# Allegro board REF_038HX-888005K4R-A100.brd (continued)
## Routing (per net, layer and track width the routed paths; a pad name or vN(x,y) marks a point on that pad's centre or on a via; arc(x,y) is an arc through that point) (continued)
1SK1_2: length 3.3
  TOP w0.231: UNK1SK1_2.1 249.83,182.77 UNK2SK1.2
1SK1_3: length 3
  TOP w0.231: UNK2SK1.3 UNK1SK1_3.1
1SK1_4: length 3.3
  TOP w0.231: UNK1SK1_4.1 249.83,188.79 UNK2SK1.4
1SK1_5: length 3.3
  TOP w0.231: UNK2SK1.5 254.65,188.79 UNK1SK1_5.1
1SK1_6: length 3
  TOP w0.231: UNK2SK1.6 UNK1SK1_6.1
1SK1_7: length 3.3
  TOP w0.231: UNK2SK1.7 254.65,182.77 UNK1SK1_7.1
1SK2_2: length 3.3
  TOP w0.231: UNK2SK2.2 266.34,182.77 UNK1SK2_2.1
1SK2_3: length 3
  TOP w0.231: UNK2SK2.3 UNK1SK2_3.1
1SK2_4: length 3.3
  TOP w0.231: UNK2SK2.4 266.34,188.79 UNK1SK2_4.1
1SK2_5: length 3.3
  TOP w0.231: UNK2SK2.5 271.16,188.79 UNK1SK2_5.1
1SK2_6: length 3
  TOP w0.231: UNK2SK2.6 UNK1SK2_6.1
1SK2_7: length 3.3
  TOP w0.231: UNK2SK2.7 271.16,182.77 UNK1SK2_7.1
CSDPS225GS1: length 221.9
  L18_POWER w0.203: SH2.2 83.05,204.25 75.9,211.4 75.9,230.22 72.28,233.83 72.28,298.16 95.49,321.36 95.49,348.54 96.17,349.22 123.34,349.22 126.06,346.5 126.06,328.87 CSDPS225.D2
CSDPS225GS3: length 96.7
  L11_POWER w0.203: CSDPS225.D4 136.19,313.65 136.19,255.89 134.92,254.62 134.92,239.9 136.33,238.49 SH24.2
CSDPS225GS5: length 117.7
  L14_POWER w0.203: SH13.2 140.82,248.47 141.96,249.62 141.96,251.82 141.52,252.27 141.52,262.31 131.87,271.96 131.87,334.79 130.27,336.39 116.51,336.39 116.01,335.88 116.01,328.76 CSDPS225.D6
CSDPS225GS7: length 96.5
  L16_POWER w0.203: CSDPS225.D8 112.03,322.44 106.91,317.32 106.91,241.73 109.74,238.9 111.81,238.9 112.66,238.05 SH8.2
CSDPS225GS9: length 186.7
  L09_POWER w0.203: SH26.2 101.66,220.34 99.34,218.02 94.61,218.02 91.99,220.65 75.25,220.65 56.67,239.23 56.67,244.65 51.45,249.87 51.45,251.38 48.13,254.7 48.13,291.4 78.84,322.11 101.4,322.11 CSDPS225.D10
CSDPS225GS11: length 145.7
  L14_POWER w0.203: CSDPS225.D12 104.1,325.43 109.92,325.43 110.92,326.43 110.92,340.61 111.86,341.55 132.11,341.55 133.05,340.61 133.05,272.45 143.87,261.63 143.87,253.56 144.32,253.11 SH15.2
CSDPS225GS13: length 225.3
  L09_POWER w0.203: SH6.2 155.68,213.34 156.32,213.97 156.32,228.24 155.72,228.84 155.72,257.92 153.76,259.88 153.76,287.44 146.76,294.43 146.76,339.29 134.19,351.86 106.81,351.86 105.75,350.8 105.75,327.58 104.67,326.51 97.94,326.51 CSDPS225.D14
  L13_CBIT w0.203: CSDPS225.A13 98.06,334.01 98.06,328.93 CSDPS225.D14 95.52,328.93 92.98,328.93 CSDPS225.D16
CSDPS225P1: length 35.2
  TOP w0.231: SITE1.3 118.52,200.86 117.21,199.55 116.14,199.55
  TOP w0.508: v1(113.47,195.75) 113.47,196.88 116.14,199.55
  L18_POWER w0.203: SH1.1 97.83,205.26 98.16,204.94 109.52,204.94 110.61,206.03 110.61,207.1 111.54,208.02 117.44,208.02 v1(118.77,206.69)
  vias: v1(94.6,264.49) v1(94.6,262.58) v1(111.81,192.9) v1(113.47,193.71)
CSDPS225P3: length 28.7
  TOP w0.231: 128.36,231.45 128.36,231.11 128.52,230.95 SITE1.105
  TOP w0.381: 128.36,231.45 128.36,233.59 129.21,234.45 v1(129.21,234.54)
  L11_POWER w0.203: v1(129.43,223.59) 130.55,222.47 132.41,222.47 134.57,224.64 134.57,231.98 137.34,234.76 SH23.1
  vias: v1(78.3,264.49) v1(78.3,262.58) v1(129.21,236.58)
CSDPS225P5: length 44
  TOP w0.231: SITE1.106 128.12,230.53 127.75,230.9 127.75,231.12
  TOP w0.381: 127.75,231.12 127.75,233.82 128.32,234.39 v1(128.32,234.54)
  L14_POWER w0.203: v1(128.23,223.59) 127.56,222.92 127.56,222.17 127.96,221.76 132.81,221.76 139.38,228.33 139.38,237.15 140.69,238.47 140.69,244.2 141.84,245.35 SH14.1
  vias: v1(78.3,244.17) v1(78.3,242.26) v1(128.32,236.58) v1(129.1,237.66)
CSDPS225P7: length 45
  TOP w0.231: SITE1.25 127.32,200.56 126.77,200.01
  TOP w0.508: v1(126.55,195.75) 126.55,198.68 126.77,198.9 126.77,200.01
  L16_POWER w0.203: SH7.1 113.68,227.62 121.76,219.55 121.76,208.6 122.56,207.8 126.46,207.8 v1(127.57,206.69)
  vias: v1(61.99,284.81) v1(61.99,282.9) v1(126.55,193.71)
CSDPS225P9: length 37.5
  TOP w0.231: 123.13,228.01 122.92,227.79 SITE1.119 ; SITE1.139 110.36,220.83 107.5,223.69 v1(106.93,223.69)
  TOP w0.508: 123.13,228.01 123.13,234.47 v1(123.06,234.54)
  L09_POWER w0.203: SH25.1 121.83,221.14 122.85,222.17 122.85,222.89 v1(122.16,223.59)
  vias: v1(51.85,264.49) v1(51.85,262.58) v1(104.89,223.69) v1(123.06,236.58)
CSDPS225P11: length 49.4
  TOP w0.231: 126.54,231.13 126.54,230.57 126.12,230.15 SITE1.111
  TOP w0.381: 126.54,231.13 v1(126.54,234.54)
  L14_POWER w0.203: SH16.1 145.33,240.67 140.56,235.9 140.56,227.84 133.83,221.1 125.84,221.1 125.24,221.7 125.24,222.71 v1(126.12,223.59)
  vias: v1(68.57,244.17) v1(68.57,242.26) v1(126.54,236.58) v1(130.1,240.04)
CSDPS225P13: length 50.6
  TOP w0.231: SITE1.64 141.98,213.63 ; 108.73,217.18 109.19,217.63 SITE1.147 ; SITE1.104 128.92,233.21 ; SITE1.39 132.92,201.49 134.03,200.37 136.06,200.37 ; SITE1.22 126.12,200.54
  TOP w0.381: 128.92,233.21 130.1,234.39 v1(130.1,234.54)
  TOP w0.508: v1(125.66,195.75) 125.66,198.96 125.87,199.17 125.87,200.28 126.12,200.54 ; 108.73,217.18 108.21,216.66 v1(106.93,216.66) ; 141.98,213.63 142.98,213.63 143.97,212.64 v1(146.71,212.64) ; v1(139.12,195.75) 139.12,197.31 136.06,200.37
  L09_POWER w0.203: v1(148.75,212.64) 148.86,212.54 SH5.1
  vias: v1(61.99,223.85) v1(61.99,221.94) v1(104.89,216.66) v1(125.66,193.71) v1(130.1,236.58) v1(134.48,213.47) v1(139.12,193.71)
CSDPS225PS1: length 219.3
  L18_POWER w0.203: SH1.2 83.04,205.26 76.61,211.7 76.61,230.68 73.07,234.22 73.07,297.93 98.11,322.97 98.11,345.75 98.79,346.42 122.6,346.42 123.41,345.61 123.41,326.84 124.27,325.98 128.13,325.98 CSDPS225.D1
CSDPS225PS3: length 96.4
  L11_POWER w0.203: SH23.2 137.34,239.05 136.83,239.56 136.83,248.36 137.21,248.73 137.21,254.5 138.43,255.72 138.43,313.96 CSDPS225.D3
CSDPS225PS5: length 133.7
  L14_POWER w0.203: CSDPS225.D5 117.84,325.85 113.92,325.85 113.41,326.36 113.41,338.27 114.14,339.01 130.6,339.01 132.45,337.15 132.45,272.2 142.1,262.55 142.1,252.51 142.54,252.06 142.54,249.19 141.84,248.48 SH14.2
CSDPS225PS7: length 97.3
  L16_POWER w0.203: CSDPS225.D7 114.57,323.94 107.65,317.01 107.65,242.04 110.05,239.64 112.12,239.64 113.68,238.08 SH7.2
CSDPS225PS9: length 186.6
  L09_POWER w0.203: CSDPS225.D9 103.07,321.24 79.2,321.24 49,291.04 49,255.06 52.32,251.74 52.32,250.23 57.54,245.01 57.54,239.59 75.61,221.52 92.35,221.52 94.97,218.89 98.98,218.89 101.23,221.14 SH25.2
CSDPS225PS11: length 148.3
  L14_POWER w0.203: SH16.2 145.33,261.03 133.66,272.7 133.66,343.41 132.95,344.11 108.69,344.11 107.98,343.41 107.98,326.9 107.38,326.3 105.77,326.3 CSDPS225.D11
CSDPS225PS13: length 232.3
  L09_POWER w0.203: SH5.2 156.29,212.54 157.14,213.39 157.14,257.82 154.7,260.27 154.7,287.83 147.71,294.82 147.71,339.68 132.98,354.41 104.04,354.41 103.16,353.54 103.16,329.54 102.55,328.92 101.45,328.92 100.19,327.66 CSDPS225.D13
  L13_CBIT w0.203: CSDPS225.A14 98.26,336.75 100.24,336.75 100.6,336.39 100.6,328.93 CSDPS225.D13 97.9,326.24 95.67,326.24 CSDPS225.D15
CSDPS229GS1: length 448.5
  L18_POWER w0.203: CSDPS229.D2 52.4,328.87 52.4,346.5 49.68,349.22 22.51,349.22 21.83,348.54 21.83,296.94 22.79,295.97 22.79,187.62 25.99,184.42 25.99,164.74 39.32,151.41 109.84,151.41 114.05,147.2 157.56,147.2 160.43,150.07 160.43,152.82 162.53,154.92 162.53,157.27 174.67,169.41 177.61,169.41 180.89,172.68 180.89,196.48 185.35,200.95 185.35,205.55 185.62,205.83 2SH2.2
CSDPS229GS3: length 243.7
  L11_POWER w0.203: 2SH24.2 216.33,238.76 214.91,240.17 214.91,254.37 169.51,299.77 169.51,313.27 130.8,351.98 84.22,351.98 57.74,325.5 50.69,325.5 CSDPS229.D4
CSDPS229GS5: length 263.7
  L14_POWER w0.203: CSDPS229.D6 42.21,328.9 42.21,340.93 42.91,341.63 57.3,341.63 62.42,346.74 137.32,346.74 161.42,322.64 192.45,322.64 218.09,297 218.09,260.47 219.1,259.46 219.1,255.13 220.82,253.41 2SH13.2
CSDPS229GS7: length 317.7
  L16_POWER w0.203: 2SH8.2 196.87,194.24 193.02,190.39 189.72,190.39 188.42,189.09 188.42,186.42 186.53,184.53 183.42,184.53 168.41,169.52 118.9,169.52 118.38,170.04 57.77,170.04 51.45,176.35 51.45,193.8 40.26,204.99 40.26,296.13 38.37,298.02 CSDPS229.D8
CSDPS229GS9: length 376.1
  L09_POWER w0.203: 2SH26.2 182.91,220.34 179.51,216.94 179.51,209.47 180.58,208.4 180.58,183.02 174.37,176.81 172.91,176.81 163.45,167.34 117.06,167.34 115.76,166.05 36.14,166.05 31.53,170.66 31.53,224.12 28.49,227.16 20.53,227.16 13.31,234.37 13.31,289.03 13.72,289.43 13.72,291.81 13.31,292.22 13.31,302.83 33.29,322.8 CSDPS229.D10
CSDPS229GS11: length 289.6
  L14_POWER w0.203: CSDPS229.D12 30.44,325.43 36.5,325.43 37.3,326.23 37.3,346.14 37.87,346.71 56.64,346.71 61.72,351.79 133.94,351.79 161.91,323.82 192.94,323.82 219.27,297.49 219.27,260.96 220.29,259.95 220.29,255.61 224.32,251.58 2SH15.2
CSDPS229GS13: length 389.7
  L09_POWER w0.203: 2SH6.2 237.8,213.47 246.49,222.16 246.49,295.89 231.96,310.42 174.54,310.42 157.35,327.61 157.35,341 136.39,361.96 70.17,361.96 60.07,351.86 33.15,351.86 32.09,350.8 32.09,327.58 31.01,326.51 24.28,326.51 CSDPS229.D14
  L13_CBIT w0.203: CSDPS229.A13 24.4,334.01 24.4,328.93 CSDPS229.D14 21.86,328.93 19.32,328.93 CSDPS229.D16
CSDPS229P1: length 22.2
  TOP w0.231: 196.14,199.55 197.21,199.55 198.52,200.86 SITE2.3
  TOP w0.508: 196.14,199.55 193.47,196.88 v1(193.47,195.75)
  L18_POWER w0.203: 2SH1.1 190.32,206.84 191.13,207.65 197.81,207.65 v1(198.77,206.69)
  vias: v1(45.28,284.81) v1(45.28,282.9) v1(191.81,192.9) v1(193.47,193.71)
CSDPS229P3: length 28.7
  TOP w0.231: SITE2.105 208.52,230.95 208.36,231.11 208.36,231.45
  TOP w0.381: v1(209.21,234.54) 209.21,234.45 208.36,233.59 208.36,231.45
  L11_POWER w0.203: v1(209.43,223.59) 210.55,222.47 212.41,222.47 214.57,224.64 214.57,231.98 217.34,234.76 2SH23.1
  vias: v1(45.28,264.49) v1(45.28,262.58) v1(209.21,236.58)
CSDPS229P5: length 44
  TOP w0.231: 207.75,231.12 207.75,230.9 208.12,230.53 SITE2.106
  TOP w0.381: v1(208.32,234.54) 208.32,234.39 207.75,233.82 207.75,231.12
  L14_POWER w0.203: v1(208.23,223.59) 207.56,222.92 207.56,222.17 207.96,221.76 212.81,221.76 219.38,228.33 219.38,237.15 220.69,238.47 220.69,244.2 221.84,245.35 2SH14.1
  vias: v1(45.28,244.17) v1(45.28,242.26) v1(208.32,236.58) v1(209.1,237.66)
CSDPS229P7: length 31.8
  TOP w0.231: SITE2.25 207.32,200.56 206.77,200.01
  TOP w0.508: v1(206.55,195.75) 206.55,198.68 206.77,198.9 206.77,200.01
  L16_POWER w0.203: 2SH7.1 195.85,197.3 197.55,198.99 197.55,208.18 198.48,209.11 205.15,209.11 v1(207.57,206.69)
  vias: v1(28.97,284.81) v1(28.97,282.9) v1(206.55,193.71)
CSDPS229P9: length 37.7
  TOP w0.231: SITE2.119 202.92,227.79 203.13,228.01 ; v1(186.93,223.69) 187.5,223.69 190.36,220.83 SITE2.139
  TOP w0.508: 203.13,228.01 203.13,234.47 v1(203.06,234.54)
  L09_POWER w0.203: v1(202.16,223.59) 202.88,222.87 202.88,221.95 202.07,221.14 2SH25.1
  vias: v1(19.24,264.49) v1(19.24,262.58) v1(184.89,223.69) v1(203.06,236.58)
CSDPS229P11: length 49.4
  TOP w0.231: 206.54,231.13 206.54,230.57 206.12,230.15 SITE2.111
  TOP w0.381: 206.54,231.13 v1(206.54,234.54)
  L14_POWER w0.203: 2SH16.1 225.33,240.67 220.56,235.9 220.56,227.84 213.83,221.1 205.84,221.1 205.24,221.7 205.24,222.71 v1(206.12,223.59)
  vias: v1(35.55,244.17) v1(35.55,242.26) v1(206.54,236.58) v1(210.1,240.04)
CSDPS229P13: length 51.8
  TOP w0.231: SITE2.64 221.98,213.63 ; SITE2.104 208.92,233.21 ; SITE2.147 189.19,217.63 188.73,217.18 ; SITE2.39 212.92,201.49 214.03,200.37 216.06,200.37 ; SITE2.22 206.12,200.54
  TOP w0.381: v1(210.1,234.54) 210.1,234.39 208.92,233.21
  TOP w0.508: 221.98,213.63 222.98,213.63 223.97,212.64 v1(226.71,212.64) ; v1(219.12,195.75) 219.12,197.31 216.06,200.37 ; v1(186.93,216.66) 188.21,216.66 188.73,217.18 ; v1(205.66,195.75) 205.66,198.96 205.86,199.17 205.86,200.28 206.12,200.54
  L09_POWER w0.203: v1(228.75,212.64) 228.78,212.66 2SH5.1
  vias: v1(28.97,223.85) v1(28.97,221.94) v1(184.89,216.66) v1(205.66,193.71) v1(210.1,236.58) v1(214.48,213.47) v1(219.12,193.71)
CSDPS229PS1: length 445.5
  L18_POWER w0.203: 2SH1.2 185.46,206.84 184.64,206.02 184.64,201.24 180.17,196.78 180.17,172.98 177.31,170.12 174.37,170.12 161.82,157.57 161.82,155.22 159.71,153.12 159.71,150.36 157.27,147.92 114.35,147.92 110.14,152.13 39.61,152.13 26.71,165.03 26.71,184.71 23.51,187.92 23.51,295.99 24.45,296.94 24.45,345.75 25.13,346.42 48.94,346.42 49.75,345.61 49.75,326.84 50.61,325.98 54.47,325.98 CSDPS229.D1
CSDPS229PS3: length 244.1
  L11_POWER w0.203: CSDPS229.D3 52.51,326.22 56.8,326.22 84.83,354.25 130.73,354.25 131.9,353.08 172.54,312.44 172.54,303.8 191.31,285.03 191.31,279.47 216.85,253.92 216.85,239.82 217.34,239.32 2SH23.2
CSDPS229PS5: length 277.6
  L14_POWER w0.203: 2SH14.2 221.84,253.21 219.68,255.37 219.68,259.7 218.67,260.71 218.67,297.24 192.7,323.22 161.66,323.22 135.76,349.12 61.73,349.12 56.68,344.07 40.34,344.07 39.55,343.27 39.55,327.67 40.86,326.35 44.68,326.35 CSDPS229.D5
CSDPS229PS7: length 314.5
  L16_POWER w0.203: CSDPS229.D7 40.91,205.26 52.1,194.07 52.1,177.95 59.37,170.68 118.37,170.68 119.42,171.73 123.76,171.73 125.13,170.36 168.34,170.36 183.15,185.18 186.26,185.18 187.78,186.69 187.78,189.36 189.45,191.04 192.75,191.04 195.85,194.14 2SH7.2
CSDPS229PS9: length 374.4
  L09_POWER w0.203: CSDPS229.D9 35.83,324.21 15.06,303.44 15.06,292.51 14.23,291.67 14.23,289.46 15.06,288.63 15.06,233.76 20.86,227.96 28.82,227.96 32.33,224.45 32.33,172.56 38.05,166.84 115.43,166.84 118.1,169.51 164.96,169.51 172.72,177.26 174.18,177.26 179.92,183.01 179.92,207.9 178.73,209.09 178.73,217.12 182.76,221.14 2SH25.2
CSDPS229PS11: length 289.9
  L14_POWER w0.203: 2SH16.2 225.33,251.43 220.89,255.87 220.89,260.2 219.88,261.22 219.88,297.74 193.2,324.43 162.16,324.43 132.37,354.22 61.38,354.22 56.67,349.51 35.91,349.51 34.56,348.16 34.56,327.14 33.72,326.3 32.11,326.3 CSDPS229.D11
CSDPS229PS13: length 397.6
  L09_POWER w0.203: CSDPS229.D13 26.53,327.66 27.79,328.92 28.89,328.92 29.5,329.54 29.5,353.54 30.38,354.41 59.02,354.41 69.09,364.48 137.44,364.48 159.87,342.04 159.87,328.65 175.58,312.94 233.01,312.94 247.19,298.76 247.19,221.87 237.98,212.66 2SH5.2
  L13_CBIT w0.203: CSDPS229.D15 22.01,326.24 24.24,326.24 CSDPS229.D13 26.94,328.93 26.94,336.39 26.58,336.75 24.6,336.75 CSDPS229.A14
CSDPS425GS1: length 156
  L09_POWER w0.203: SH11.2 153.28,218.83 153.48,219.03 153.48,228.47 154.25,229.24 154.25,254.35 146.54,262.07 146.54,291.27 137.57,300.23 137.57,345.56 135.48,347.65 128.73,347.65 127.87,346.79 126.98,346.79 126.27,346.07 126.27,338.82 CSDPS425.D2
CSDPS425GS3: length 244.7
  L20_SIGNAL w0.203: SH19.2 111.82,138.74 89.77,160.79 88.55,160.79 87.05,162.29 87.05,163.68 76.95,173.78 76.95,234.44 73.74,237.65 73.74,274.49 81.97,282.72 81.97,299.83 106.68,324.54 118.85,324.54 120.96,326.65 120.96,336.59 CSDPS425.D4
CSDPS425GS7: length 122.5
  L11_POWER w0.203: SH17.2 139.61,238.46 138.79,239.29 138.79,245.47 138.96,245.64 138.96,252.74 139.54,253.32 139.54,327.51 130.51,336.55 113.3,336.55 CSDPS425.D8
CSDPS425GS9: length 340.2
  L20_SIGNAL w0.203: CSDPS425.D10 105.71,336.58 105.71,325.9 80.31,300.49 80.31,283.41 71.9,275 71.9,173.2 87.96,157.14 87.96,137.69 99.43,126.22 127.46,126.22 137.57,136.34 137.57,165.34 135.49,167.42 135.49,176.93 136.71,178.15 136.71,194.54 136.63,194.62 SH21.2
CSDPS425GS11: length 158.4
  L18_POWER w0.203: CSDPS425.D12 100.58,336.53 100.58,323.61 74.2,297.22 74.2,234.36 77.33,231.23 77.33,216.12 81.07,212.38 86.1,212.38 89.73,208.75 96.07,208.75 97.08,209.77 SH4.2
CSDPS425GS13: length 128.9
  L16_POWER w0.203: SH9.2 131.53,240.11 126.58,245.06 123.41,245.06 118.05,250.42 118.05,335.7 117.53,336.22 98.39,336.22 CSDPS425.D14
CSDPS425GS15: length 240.9
  L11_POWER w0.203: CSDPS425.D16 92.92,336.61 99.59,336.61 100.62,337.64 100.62,346.52 97.9,349.24 85.12,349.24 66.15,330.27 66.15,320.44 48.47,302.75 48.47,222.23 58.89,211.81 87.06,211.81 87.69,211.18 103.72,211.18 104.61,210.29 SH28.2
CSDPS425P1: length 22.6
  TOP w0.231: v1(135.14,234.54) 135.14,234.13 131.72,230.71 SITE1.97 ; SITE1.78 139.64,219.23 139.86,219.01
  TOP w0.508: 139.86,219.01 145.8,219.01 146.29,219.5 v1(146.71,219.5)
  L09_POWER w0.203: SH12.1 150.23,218.03 v1(148.75,219.5)
  vias: v1(61.58,264.49) v1(61.58,262.58) v1(134.48,219.47) v1(135.14,236.58)
CSDPS425P3: length 12.1
  L20_SIGNAL w0.203: v1(120.06,130.5) 119.88,130.32 114,130.32 112.84,131.48 SH20.1
  vias: v1(86.73,295.44) v1(86.73,293.53) v1(123.26,130.5)
CSDPS425P7: length 31.6
  TOP w0.231: 144.04,216.19 143.41,216.83 SITE1.72
  TOP w0.508: 144.04,216.19 145.05,215.18 v1(146.71,215.18)
  L11_POWER w0.203: 134.71,216.89 134.71,218.59 137,220.88 137,231.23 140.63,234.86 SH18.1
  vias: v1(61.58,244.17) v1(61.58,242.26) v1(134.48,216.67) v1(148.75,215.18)
CSDPS425P9: length 59.1
  L20_SIGNAL w0.203: SH22.1 135.62,199.42 138.33,202.14 157.46,202.14 165.42,194.18 165.42,179.57 v1(163.84,177.99)
  BOTTOM w0.508: U1.8 C8.1 ; U2.8 C9.1
  vias: v1(38.08,172.27) v1(45.45,188.37) v1(45.44,172.27) v1(54.2,134.91) v1(56.92,131.75) v1(56.92,130.61) v1(66.06,150.04) v1(66.06,147.5) v1(66.06,144.96) v1(70.86,134.91) v1(72.59,131.75) v1(72.59,130.61) v1(78.65,295.51) v1(78.65,293.6) v1(85.77,150.04) v1(85.77,147.5) v1(85.77,144.96) v1(156.45,177.99)
CSDPS425P11: length 85.3
  TOP w0.231: 140.69,212.93 140.38,213.23 SITE1.63 ; 127.18,231.16 127.18,230.65 127.72,230.11 SITE1.107 ; 124.77,198.85 124.12,199.5 SITE1.17 ; SITE1.37 132.12,201.59 134.06,199.66 135.22,199.66 ; SITE1.162 110.12,211.63 ; 143.33,215.53 142.43,216.43 SITE1.71 ; 108.32,218.18 108.57,218.43 SITE1.145
  TOP w0.381: 127.18,231.16 127.18,234.28 v1(127.43,234.54)
  TOP w0.508: 140.69,212.93 140.94,212.67 142.29,212.67 143.6,211.37 v1(146.71,211.37) ; v1(137.85,195.75) 137.85,197.02 135.22,199.66 ; v1(106.93,217.93) 108.07,217.93 108.32,218.18 ; v1(146.71,213.91) 144.94,213.91 143.33,215.53 ; 124.77,198.85 v1(124.77,195.75) ; v1(106.93,213.41) 108.08,213.41 109.86,211.63 110.12,211.63
  L18_POWER w0.203: SH3.1 110.46,210.79 112.2,209.04 117.3,209.04 117.77,209.52 117.77,211.22 v1(117.36,211.63)
  vias: v1(56.69,178.19) v1(84.87,264.49) v1(84.87,262.58) v1(104.89,217.93) v1(104.89,213.41) v1(124.77,193.71) v1(127.43,236.58) v1(137.85,193.71) v1(148.75,213.91) v1(148.75,211.37)
CSDPS425P13: length 38.2
  TOP w0.231: SITE1.31 129.72,198.29 130.16,197.85
  TOP w0.508: 130.16,197.85 v1(132.26,195.75)
  L16_POWER w0.203: v1(129.97,206.69) 131.96,208.68 131.96,220.63 132.55,221.21 SH10.1
  vias: v1(52.26,284.81) v1(52.26,282.9) v1(132.26,193.71)
CSDPS425P15: length 26.3
  TOP w0.231: SITE1.144 107.69,218.83
  TOP w0.508: 107.69,218.83 107.3,218.83 v1(106.93,219.2)
  L11_POWER w0.203: SH27.1 110.85,211.31 111.65,212.11 116.35,212.11 116.79,212.56 117.75,212.56 119.02,213.82 119.02,217.93 118.79,218.15 118.04,218.15 v1(117.36,218.83)
  vias: v1(51.85,244.17) v1(51.85,242.26) v1(104.89,219.2)
CSDPS425PS1: length 170.3
  L09_POWER w0.203: CSDPS425.D1 128.75,336.76 124.21,336.76 123.48,337.49 123.48,347.9 124.76,349.18 135.12,349.18 138.24,346.06 138.24,300.21 146.99,291.46 146.99,262.26 154.85,254.4 154.85,228.76 154.1,228 154.1,218.52 153.61,218.03 SH12.2
CSDPS425PS3: length 246.1
  L20_SIGNAL w0.203: CSDPS425.D3 123.58,336.67 123.58,326.9 120.1,323.42 106.76,323.42 83.09,299.75 83.09,282.26 74.68,273.85 74.68,238.25 77.77,235.17 77.77,174.29 87.99,164.07 87.99,162.68 88.94,161.73 90.16,161.73 112.84,139.06 SH20.2
CSDPS425PS7: length 123.2
  L11_POWER w0.203: CSDPS425.D7 115.39,337.82 116.54,338.97 130.61,338.97 141.3,328.28 141.3,252.59 140.15,251.45 140.15,246.21 140.69,245.67 140.69,240.1 140.63,240.04 SH18.2
CSDPS425PS9: length 338.2
  L20_SIGNAL w0.203: CSDPS425.D9 108.29,336.62 108.29,327.36 81.09,300.17 81.09,283.08 72.87,274.86 72.87,213.26 73.66,212.46 73.66,172.8 88.93,157.54 88.93,138.09 99.83,127.19 127.06,127.19 136.77,136.9 136.77,165 134.23,167.54 134.23,176.81 135.9,178.48 135.9,188.95 135.9,188.96 135.9,194.49 135.62,194.78 SH22.2
CSDPS425PS11: length 154.4
  L18_POWER w0.203: CSDPS425.D11 103.08,336.49 103.08,325.09 80.84,302.85 80.84,237.28 78.05,234.49 78.05,216.42 81.37,213.1 87.86,213.1 90.17,210.79 SH3.2
CSDPS425PS13: length 129.3
  L16_POWER w0.203: SH10.2 132.55,238.04 132.99,238.48 132.99,244.24 122.8,254.43 122.8,266.58 121.01,268.37 121.01,337.98 120.03,338.97 100.47,338.97 CSDPS425.D13
CSDPS425PS15: length 225.5
  L11_POWER w0.203: CSDPS425.D15 95.4,338.97 97.38,338.97 98.06,339.65 98.06,345.81 97.22,346.65 85.3,346.65 68.74,330.1 68.74,321.97 49.21,302.45 49.21,222.54 59.2,212.55 103.4,212.55 104.96,210.98 105.81,210.98 106.14,211.31 SH27.2
CSDPS429GS1: length 311.9
  L09_POWER w0.203: CSDPS429.D2 52.61,338.82 52.61,346.07 53.32,346.79 54.21,346.79 55.53,348.11 62.28,348.11 71.05,356.88 134.29,356.88 152.28,338.9 152.28,325.51 172.44,305.35 229.86,305.35 243.43,291.78 243.43,227.77 240.32,224.66 240.32,222.55 239.44,221.67 2SH11.2
CSDPS429GS5: length 414.9
  L20_SIGNAL w0.203: CSDPS429.D6 42.36,336.73 42.36,308.46 40.24,306.34 40.24,209.21 33.52,202.49 27.81,202.49 25.22,199.9 25.22,145.69 66.93,103.97 152.73,103.97 166.22,117.46 202,117.46 207.11,122.57 2SH19.2
CSDPS429GS7: length 257.4
  L11_POWER w0.203: 2SH17.2 219.61,238.98 218.77,239.82 218.77,268.55 133.56,353.76 130.52,356.8 86.01,356.8 65.67,336.46 39.73,336.46 CSDPS429.D8
CSDPS429GS9: length 502.3
  L20_SIGNAL w0.203: 2SH21.2 221.37,190.44 222.65,189.15 222.65,181.24 224.07,179.83 224.07,149.6 225.86,147.81 225.86,132.6 223.69,130.43 223.69,127.48 200.87,104.67 155.31,104.67 153.35,102.7 66.41,102.7 22.72,146.39 22.72,170.3 21.08,171.94 21.08,176.77 22.89,178.59 22.89,199.85 26.9,203.85 31.78,203.85 38.15,210.22 38.15,237 38.97,237.82 38.97,252.15 38.18,252.94 38.18,257.07 38.97,257.86 38.97,273.29 38.06,274.2 38.06,278.66 38.96,279.56 38.96,296.7 34.48,301.18 34.48,336.63 CSDPS429.D10
CSDPS429GS11: length 380.2
  L18_POWER w0.203: CSDPS429.D12 26.92,336.53 26.92,297.27 24.25,294.6 24.25,278.54 25.51,277.28 25.51,275.44 24.36,274.29 24.36,257.65 25.56,256.45 25.56,254.72 24.33,253.49 24.33,237.27 25.39,236.21 25.39,234.42 24.36,233.38 24.36,218.03 27.75,214.64 27.75,167.63 40.68,154.7 111.21,154.7 114.69,151.22 150.29,151.22 151.02,151.95 155.72,151.95 158.44,154.68 158.44,156.75 173.19,171.49 173.19,174.84 178.05,179.7 178.05,198.25 180.39,200.59 180.39,207.03 182.47,209.11 2SH4.2
CSDPS429GS13: length 482.3
  L16_POWER w0.203: 2SH9.2 216.83,185.68 216.08,184.93 216.08,180.64 219.82,176.9 219.82,161.42 218.09,159.68 197.06,159.68 174.25,136.87 89.9,136.87 86.33,140.45 44.78,140.45 12.8,172.43 12.8,283.1 9.46,286.44 9.46,298.93 14.02,303.48 14.02,321.4 11.12,324.29 11.12,345.81 14.62,349.31 29.56,349.31 32,346.86 32,337.28 31.32,336.6 24.35,336.6 CSDPS429.D14
CSDPS429GS15: length 462.1
  L11_POWER w0.203: CSDPS429.D16 19.26,336.61 25.93,336.61 26.96,337.64 26.96,346.52 24.24,349.24 11.44,349.24 6.33,344.13 6.33,323.15 12.66,316.82 12.66,304.89 8.41,300.63 8.41,281.07 12.66,276.82 12.66,162.13 34.18,140.61 87.69,140.61 91.92,136.38 157.63,136.38 164.63,143.37 164.63,145.85 165.76,146.98 172.7,146.98 183.74,158.02 183.74,174.89 195.61,186.76 2SH28.2
CSDPS429P1: length 28.3
  TOP w0.231: SITE2.97 211.72,230.71 215.14,234.13 v1(215.14,234.54) ; 219.86,219.01 219.64,219.23 SITE2.78
  TOP w0.508: v1(226.71,219.5) 226.29,219.5 225.8,219.01 219.86,219.01
  L09_POWER w0.203: v1(228.75,219.5) 229.28,218.97 233.13,218.97 235.03,220.87 2SH12.1
  vias: v1(28.97,264.49) v1(28.97,262.58) v1(214.48,219.47) v1(215.14,236.58)
CSDPS429P5: length 4.4
  L20_SIGNAL w0.203: 2SH20.1 206.09,129.94 205.57,130.46 203.3,130.46 v1(203.26,130.5)
  vias: v1(47.18,295.44) v1(47.18,293.53) v1(200.06,130.5)
CSDPS429P7: length 31.9
  TOP w0.231: 224.04,216.19 223.41,216.83 SITE2.72
  TOP w0.508: v1(226.71,215.18) 225.05,215.18 224.04,216.19
  L11_POWER w0.203: 2SH18.1 220.63,234.86 217,231.23 217,220.88 214.71,218.59 214.71,216.89 v1(214.48,216.67)
  vias: v1(28.97,244.17) v1(28.97,242.26) v1(228.75,215.18)
CSDPS429P9: length 48.7
  L20_SIGNAL w0.203: 2SH22.1 220.35,195.65 219.41,196.59 219.41,199.75 232.75,213.08 240.35,213.08 241.08,212.35 246.51,212.35 246.89,211.98 246.89,209.83 v1(247.26,209.45)
  BOTTOM w0.508: UNK2U2.8 UNK2C9.1 ; UNK2U1.8 UNK2C8.1
  vias: v1(35.47,295.51) v1(35.47,293.6) v1(236.45,177.99) v1(239.88,193.35) v1(243.84,177.99) v1(247.17,174.02) v1(247.17,171.48) v1(247.17,168.94) v1(247.25,193.35) v1(260.35,188.37) v1(260.35,187.23) v1(262.07,184.06) v1(266.88,174.02) v1(266.88,171.48) v1(266.88,168.94) v1(276.01,188.37) v1(276.01,187.23) v1(278.74,184.06)
CSDPS429P11: length 77.2
  TOP w0.231: 220.69,212.93 220.38,213.23 SITE2.63 ; SITE2.162 190.12,211.63 ; SITE2.107 207.72,230.11 207.18,230.65 207.18,231.16 ; 188.32,218.18 188.57,218.43 SITE2.145 ; SITE2.71 222.43,216.43 223.33,215.53 ; SITE2.17 204.12,199.5 204.77,198.85 ; SITE2.37 212.12,201.59 214.06,199.66 215.22,199.66
  TOP w0.381: v1(207.43,234.54) 207.18,234.28 207.18,231.16
  TOP w0.508: 190.12,211.63 189.86,211.63 188.08,213.41 v1(186.93,213.41) ; 215.22,199.66 217.85,197.02 v1(217.85,195.75) ; 220.69,212.93 220.94,212.67 222.29,212.67 223.6,211.37 v1(226.71,211.37) ; 223.33,215.53 224.94,213.91 v1(226.71,213.91) ; 204.77,198.85 v1(204.77,195.75) ; 188.32,218.18 188.07,217.93 v1(186.93,217.93)
  L18_POWER w0.203: 2SH3.1 184.88,210.13 185.3,210.55 188.97,210.55 189.3,210.22 195.95,210.22 v1(197.36,211.63)
  vias: v1(35.55,284.81) v1(35.55,282.9) v1(184.89,217.93) v1(184.89,213.41) v1(204.77,193.71) v1(207.43,236.58) v1(217.85,193.71) v1(228.75,213.91) v1(228.75,211.37) v1(256.47,199.28)
CSDPS429P13: length 31.1
  TOP w0.231: 210.16,197.85 209.72,198.29 SITE2.31
  TOP w0.508: 210.16,197.85 v1(212.26,195.75)
  L16_POWER w0.203: v1(209.97,206.69) 210.93,207.64 214.65,207.64 215.09,207.21 215.09,205.92 215.81,205.2 2SH10.1
  vias: v1(19.24,284.81) v1(19.24,282.9) v1(212.26,193.71)
CSDPS429P15: length 37.1
  TOP w0.231: SITE2.144 187.69,218.83
  TOP w0.508: 187.69,218.83 187.3,218.83 v1(186.93,219.2)
  L11_POWER w0.203: 2SH27.1 194.59,210.54 196.61,212.56 197.68,212.56 198.97,213.85 198.97,217.98 198.75,218.19 198,218.19 v1(197.36,218.83)
  vias: v1(19.24,244.17) v1(19.24,242.26) v1(184.89,219.2)
CSDPS429PS1: length 328.6
  L09_POWER w0.203: CSDPS429.D1 55.09,336.76 50.55,336.76 49.82,337.49 49.82,347.9 51.1,349.18 61.19,349.18 71.44,359.44 135.35,359.44 154.83,339.95 154.83,326.56 173.49,307.9 230.92,307.9 244.19,294.63 244.19,227.45 241.08,224.35 241.08,222.24 239.71,220.87 2SH12.2
CSDPS429PS5: length 413.4
  L20_SIGNAL w0.203: CSDPS429.D5 44.86,336.69 44.86,310.07 40.88,306.08 40.88,208.94 33.79,201.85 28.14,201.85 25.85,199.57 25.85,145.95 67.2,104.61 152.47,104.61 165.96,118.1 201.73,118.1 206.09,122.46 2SH20.2
CSDPS429PS7: length 262.9
  L11_POWER w0.203: CSDPS429.D7 41.9,337.82 43.25,339.17 66.88,339.17 86.94,359.23 130.07,359.23 134.96,354.34 172.82,316.48 182.34,316.48 219.57,279.25 219.57,245.51 220.7,244.39 220.7,239.82 220.63,239.75 2SH18.2
CSDPS429PS9: length 499
  L20_SIGNAL w0.203: CSDPS429.D9 37.13,336.52 37.13,299.42 39.6,296.96 39.6,279.29 38.7,278.39 38.7,274.46 39.61,273.56 39.61,257.6 38.81,256.81 38.81,253.2 39.61,252.41 39.61,237.56 38.78,236.74 38.78,209.96 32.04,203.22 27.16,203.22 23.53,199.58 23.53,177.91 24.18,177.25 24.18,174.72 23.36,173.89 23.36,146.66 66.67,103.34 153.09,103.34 155.05,105.3 200.61,105.3 223.05,127.74 223.05,130.69 225.22,132.86 225.22,147.54 223.43,149.33 223.43,179.57 220,183 220,186.27 220.35,186.62 2SH22.2
CSDPS429PS11: length 380.5
  L18_POWER w0.203: 2SH3.2 182.35,210.13 179.67,207.45 179.67,200.89 177.34,198.55 177.34,180 172.48,175.14 172.48,171.79 157.73,157.04 157.73,154.97 155.42,152.67 150.73,152.67 150,151.93 114.98,151.93 111.5,155.41 40.98,155.41 28.46,167.93 28.46,214.95 25.28,218.13 25.28,232.8 26.74,234.25 26.74,236.23 25.2,237.77 25.2,252.42 26.82,254.05 26.82,256.73 25.17,258.38 25.17,273.09 26.34,274.26 26.34,277.87 25.17,279.04 25.17,293.89 29.42,298.14 29.42,336.49 CSDPS429.D11
CSDPS429PS13: length 465.6
  L16_POWER w0.203: 2SH10.2 215.81,185.89 215.62,185.7 215.62,180.45 219.36,176.71 219.36,161.61 217.9,160.14 196.87,160.14 174.06,137.33 90.09,137.33 86.52,140.9 44.97,140.9 13.64,172.24 13.64,283.4 10.23,286.8 10.23,298.36 14.78,302.91 14.78,321.95 12,324.73 12,343.95 14.79,346.74 28.63,346.74 29.38,345.99 29.38,339.67 28.7,338.99 26.84,338.99 CSDPS429.D13
CSDPS429PS15: length 446.1
  L11_POWER w0.203: CSDPS429.D15 21.74,338.97 23.72,338.97 24.4,339.65 24.4,345.81 23.56,346.65 9.86,346.65 7.05,343.84 7.05,323.45 13.38,317.12 13.38,304.09 9.39,300.11 9.39,281.67 13.38,277.69 13.38,162.43 34.47,141.33 87.99,141.33 92.22,137.1 157.33,137.1 163.91,143.67 163.91,146.15 165.46,147.7 172.4,147.7 183.02,158.32 183.02,175.19 194.59,186.75 2SH27.2
D10301: length 209.5
  TOP w0.231: SITE1.70 140.32,216.03 v1(141.32,215.03)
  L07_SIGNAL w0.17: D103.01 160.04,58.67 160.04,89.46 164.39,93.82 181.57,93.82 183.35,95.6 183.35,131.83 184.22,132.71 184.22,133.8 183.51,134.51 183.51,136.81 184.31,137.6 184.31,158.19 172.64,169.86 172.64,191.89 160.84,203.7 160.84,206.63 153.8,213.67 150.34,213.67 149.46,214.54 144.79,214.54 144.53,214.28 142.07,214.28 v1(141.32,215.03)
D10302: length 209.8
  TOP w0.231: SITE1.65 141.54,214.03 142.54,215.03 v1(142.71,215.03)
  L07_SIGNAL w0.17: D103.02 160.8,62.99 160.8,88.72 165.07,92.99 182.38,92.99 185.62,96.23 185.62,128.63 184.63,129.62 184.63,131.53 185.51,132.41 185.51,159.72 173.47,171.76 173.47,192.29 161.82,203.94 161.82,206.82 154.14,214.5 150.83,214.5 149.52,215.81 143.5,215.81 v1(142.71,215.03)
D10303: length 215.3
  TOP w0.231: SITE1.66 139.52,214.43 139.92,214.83 v1(139.92,215.03)
  L07_SIGNAL w0.17: v1(139.92,215.03) 141.68,213.27 149.45,213.27 149.94,212.78 153.43,212.78 159.77,206.44 159.77,203.26 162.64,200.4 162.64,192.3 170.71,184.22 170.71,168.34 183.07,155.98 183.07,138.09 181.98,137 181.98,132.68 181.08,131.78 181.08,129.43 181.76,128.74 181.76,96.04 180.56,94.84 163.77,94.84 159.27,90.34 159.27,57.18 161.83,54.63 166.66,54.63 D103.03
D10304: length 123.9
  L05_SIGNAL w0.145: D103.04 169.17,59.7 159.54,59.7 128.09,28.25 85,28.25 70.33,13.59 v1(68.81,13.59)
  BOTTOM w0.231: UB1.6 v1(68.81,13.59)
D10305: length 282.8
  TOP w0.231: v1(139.92,212.23) 139.72,212.43 SITE1.61
  L07_SIGNAL w0.17: v1(139.92,212.23) 140.15,212 152.66,212 158.56,206.11 158.56,202.29 160.36,200.49 160.36,193.31 168.33,185.34 168.33,159.62 169.86,158.09 169.86,101.57 170.25,101.18 170.95,101.18 171.39,101.62 171.39,131.54 172.36,132.5 177.21,132.5 178.23,131.48 178.23,97.54 176.84,96.15 163.08,96.15 158.51,91.57 158.51,54.03 160.74,51.81 168.92,51.81 D103.05
D10306: length 128.6
  L05_SIGNAL w0.145: v1(68.81,12.06) 70.96,12.06 85.63,26.73 128.73,26.73 159.14,57.15 174.26,57.15 D103.06
  BOTTOM w0.231: UB1.5 68.87,12.13 v1(68.81,12.06)
D10307: length 282.8
  TOP w0.231: SITE1.59 141.71,211.63 v1(142.71,210.63)
  L07_SIGNAL w0.17: D103.07 173.24,51.05 160.42,51.05 157.75,53.72 157.75,92.37 162.53,97.16 175.01,97.16 176.13,98.28 176.13,129.58 175.56,130.15 172.89,130.15 172.41,129.67 172.41,100.94 171.71,100.24 169.62,100.24 168.6,101.26 168.6,149.84 168.18,150.26 168.18,158.5 167.43,159.25 167.43,185.09 159.46,193.06 159.46,200.01 157.52,201.95 157.52,205.64 152.53,210.63 v1(142.71,210.63)
D10309: length 282.8
  TOP w0.231: v1(141.32,210.63) 140.72,211.23 SITE1.58
  L07_SIGNAL w0.17: D103.09 177.55,50.29 160.1,50.29 156.99,53.4 156.99,93.34 161.62,97.98 173.57,97.98 175.04,99.44 175.04,126.38 174.63,126.79 173.91,126.79 173.49,126.38 173.49,100.39 172.43,99.32 168.27,99.32 167.23,100.36 167.23,156.94 165.35,158.82 165.35,184.52 158.66,191.21 158.66,199.74 156.33,202.07 156.33,203.92 154.91,205.34 154.91,206.4 152.98,208.34 151.82,208.34 151.46,207.97 146.06,207.97 144.2,209.83 142.11,209.83 v1(141.32,210.63)
D10311: length 215.4
  TOP w0.231: v1(142.71,209.03) 141.71,210.03 SITE1.55
  L07_SIGNAL w0.17: v1(142.71,209.03) 143.64,209.03 145.54,207.13 151.8,207.13 155.09,203.84 155.09,202.03 157.84,199.28 157.84,191.04 164.53,184.35 164.53,158.48 165.54,157.47 165.54,152.33 166.14,151.73 166.14,147.59 165.96,147.41 165.96,104.02 156.23,94.28 156.23,53.09 159.79,49.52 181.87,49.52 D103.11
D10313: length 220.9
  TOP w0.231: v1(141.32,209.03) 140.72,209.63 SITE1.54
  L07_SIGNAL w0.17: D103.13 185.8,48.37 159.35,48.37 155.43,52.28 155.43,95.16 164.67,104.39 164.67,149.59 164.08,150.18 164.08,153.88 162.96,155 162.96,184.92 157.06,190.82 157.06,198.5 154.33,201.24 154.33,203.42 152.82,204.93 146.2,204.93 142.88,208.25 142.09,208.25 v1(141.32,209.03)
D10315: length 282.8
  TOP w0.231: v1(135.72,214.63) 135.92,214.83 SITE1.67
  L03_SIGNAL w0.145: K13.3 160.24,180.7 160.24,191.54 152.49,199.29 152.49,203.67 142.01,214.15 138.81,214.15 138.34,214.63 v1(135.72,214.63)
  L07_SIGNAL w0.17: D103.15 197.33,54.82 197.33,50.02 194.92,47.6 159.03,47.6 154.33,52.3 154.33,95.93 157.93,99.53 157.93,125.06 158.2,125.33 159.63,125.33 159.93,125.04 159.93,103.76 160.36,103.32 162.05,103.32 163.48,104.75 163.48,146.87 162.99,147.37 162.99,152.4 162.21,153.17 162.21,162.29 159.95,164.55 159.95,177.39 K13.3
D10401: length 282.8
  TOP w0.231: SITE1.56 135.92,210.43 v1(135.72,210.23)
  L07_SIGNAL w0.17: v1(135.72,210.23) 136.44,209.5 136.44,200.07 135.69,199.32 135.69,181.78 149.62,167.85 149.62,161.57 149.24,161.19 149.24,157.97 148.04,156.77 148.04,128.72 136.31,116.99 136.31,27.32 137.61,26.03 155.86,26.03 156.65,26.82 156.65,31.68 156.35,31.98 149.61,31.98 149.39,32.2 149.39,33.87 149.74,34.21 156.33,34.21 156.65,34.53 156.65,36.71 156.19,37.17 142.99,37.17 142.35,37.82 142.35,39.21 143.15,40.02 160.65,40.02 161.44,39.23 161.44,35.73 161.61,35.56 D104.01
D10402: length 282.8
  TOP w0.231: SITE1.60 135.92,212.03 v1(135.72,211.83)
  L07_SIGNAL w0.17: v1(135.72,211.83) 137.07,210.48 137.07,199.44 136.38,198.75 136.38,182.06 150.96,167.48 150.96,163.76 150.73,163.53 150.73,156.7 149.2,155.17 149.2,128.36 137.07,116.23 137.07,43.64 138.03,42.69 141.81,42.69 142.56,43.43 142.56,77.28 142.9,77.63 143.55,77.63 143.83,77.35 143.83,42.52 145.45,40.9 162.57,40.9 D104.02
D10403: length 282.8
  TOP w0.231: SITE1.48 135.92,207.23 v1(135.72,207.03)
  L07_SIGNAL w0.17: D104.03 169.14,34.33 169.14,32.3 168.65,31.82 158.78,31.82 158.18,31.22 158.18,28.44 158.71,27.91 180.37,27.91 180.8,27.48 180.8,26.02 180.09,25.3 136.72,25.3 135.55,26.47 135.55,117.75 147.11,129.32 147.11,157.75 148.29,158.92 148.29,167.33 134.41,181.2 134.41,199.5 135.66,200.75 135.66,206.97 v1(135.72,207.03)
D10404: length 282.8
  TOP w0.231: v1(139.92,210.63) 139.72,210.83 SITE1.57
  L07_SIGNAL w0.17: D104.04 166.51,42.04 146.08,42.04 144.8,43.32 144.8,78.12 144.2,78.72 142.37,78.72 141.65,77.99 141.65,46.05 141.08,45.48 138.31,45.48 137.83,45.95 137.83,115.47 150.33,127.97 150.33,154.97 152.2,156.84 152.2,167.21 137.06,182.35 137.06,198.31 137.7,198.95 137.7,208.41 v1(139.92,210.63)
D10405: length 282.8
  TOP w0.231: v1(135.72,208.63) 135.92,208.83 SITE1.52
  L07_SIGNAL w0.17: v1(135.72,208.63) 134.96,207.87 134.96,202.67 133.73,201.44 133.73,180.92 145.09,169.56 145.09,165.12 145.94,164.27 145.94,161.87 145.57,161.5 145.57,129.3 134.79,118.51 134.79,26.15 136.4,24.54 180.57,24.54 181.64,25.61 181.64,27.9 180.79,28.75 161.56,28.75 161.23,29.08 161.23,30.33 161.63,30.74 170.34,30.74 171.15,31.54 171.15,33.72 D104.05
D10406: length 282.8
  TOP w0.231: SITE1.53 139.72,209.23 v1(139.92,209.03)
  L07_SIGNAL w0.17: v1(139.92,209.03) 138.49,207.6 138.49,197.33 139.79,196.03 139.79,193 138.96,192.18 138.96,182.98 152.97,168.98 152.97,164.48 153.36,164.08 153.36,155.73 152.14,154.5 152.14,128.24 138.6,114.7 138.6,48.12 139,47.72 140.37,47.72 140.6,47.95 140.6,78.79 141.52,79.71 144.94,79.71 145.93,78.71 145.93,43.76 146.66,43.03 170.6,43.03 D104.06
D10407: length 254
  TOP w0.231: v1(133.12,205.23) 133.32,205.03 SITE1.40
  L07_SIGNAL w0.17: v1(133.12,205.23) 133.12,202.78 132.31,201.98 132.31,196.9 132.98,196.23 132.98,180.61 142.5,171.09 142.5,167.65 143.87,166.29 143.87,162.66 144.77,161.76 144.77,130.02 134.02,119.28 134.02,25.84 136.08,23.78 181.66,23.78 182.55,24.67 182.55,31.08 D104.07
D10408: length 206.5
  TOP w0.231: SITE1.49 139.72,207.63 v1(139.92,207.43)
  L07_SIGNAL w0.17: D104.08 174.92,43.79 157.45,43.79 146.74,54.5 146.74,121.33 153.06,127.64 153.06,154.03 154.73,155.71 154.73,168.21 139.66,183.27 139.66,191.95 140.44,192.73 140.44,196.3 139.15,197.6 139.15,206.65 v1(139.92,207.43)
D10409: length 265
  L07_SIGNAL w0.17: D104.09 186.21,32.5 186.21,23.96 185.27,23.01 135.77,23.01 133.26,25.52 133.26,122.32 143.06,132.12 143.06,164.68 141.78,165.97 141.78,169.94 131.34,180.38 131.34,202.24 132.49,203.39 132.49,212.48 v1(133.48,213.47)
D10410: length 209.2
  TOP w0.231: SITE1.45 139.72,206.03 v1(139.92,205.83)
  L07_SIGNAL w0.17: D104.10 179.23,44.56 157.77,44.56 147.5,54.82 147.5,120.56 154.56,127.62 154.56,154.02 155.69,155.15 155.69,159.09 155.99,159.39 155.99,163.48 155.45,164.01 155.45,168.51 140.39,183.57 140.39,191.58 141.22,192.41 141.22,196.62 139.92,197.92 v1(139.92,205.83)
D10411: length 282.8
  TOP w0.231: SITE1.69 133.93,215.63 v1(132.92,214.63)
  L07_SIGNAL w0.17: v1(132.92,214.63) 131.23,212.94 131.23,203.11 130.65,202.53 130.65,180.09 140.73,170.01 140.73,165.54 142.34,163.93 142.34,132.92 132.5,123.09 132.5,25.21 135.45,22.25 192.28,22.25 193.48,23.45 193.48,31.61 193.15,31.94 191.1,31.94 188.23,34.81 D104.11
D10412: length 217.8
  TOP w0.231: v1(141.32,205.83) 140.72,206.43 SITE1.46
  L07_SIGNAL w0.17: D104.12 183.55,45.32 158.08,45.32 148.36,55.04 148.36,119.9 155.51,127.05 155.51,152.44 157.26,154.18 157.26,163.61 157.56,163.91 157.56,168.72 153.26,173.01 153.26,196.15 149.75,199.66 144.11,199.66 141.32,202.45 v1(141.32,205.83)
D10413: length 279.1
  L07_SIGNAL w0.17: D104.13 194.67,34.2 194.67,23 193.11,21.44 135.12,21.44 131.74,24.81 131.74,123.55 140.05,131.86 140.05,163.15 139.34,163.86 139.34,170.38 129.9,179.82 129.9,202.89 130.56,203.56 130.56,213.75 v1(133.48,216.67)
D10414: length 224.4
  TOP w0.231: SITE1.47 141.71,206.83 v1(142.71,205.83)
  L07_SIGNAL w0.17: v1(142.71,205.83) 142.71,202.29 144.64,200.36 150.16,200.36 154.04,196.49 154.04,173.34 158.33,169.04 158.33,163.88 159.87,162.34 159.87,158.96 158.31,157.39 158.31,153.08 157.06,151.82 157.06,127.07 149.16,119.17 149.16,55.32 158.4,46.08 187.87,46.08 D104.14
D10415: length 301.3
  TOP w0.231: v1(106.4,215.39) 108.12,215.39 109.65,216.91 112.79,216.91 113.11,217.23 SITE1.148
  L07_SIGNAL w0.17: v1(106.4,215.39) 107.52,215.39 108.78,214.12 108.78,211.91 123.84,196.85 123.84,193.55 125.67,191.72 125.67,177.66 137.34,165.99 137.34,130.85 130.98,124.48 130.98,24.38 134.77,20.59 198.01,20.59 199.86,22.45 199.86,34.09 D104.15
D10416: length 282.8
  TOP w0.231: SITE1.68 134.92,215.23 v1(134.32,214.63)
  L03_SIGNAL w0.145: v1(134.32,214.63) 135.22,213.73 137.96,213.73 138.44,213.25 141.63,213.25 151.59,203.3 151.59,198.92 155.06,195.44 155.06,188.64 157.02,186.68 157.02,180.71 K13.6
  L07_SIGNAL w0.17: D104.16 192.19,46.84 158.71,46.84 153.51,52.05 153.51,96.72 156.99,100.2 156.99,125.48 157.98,126.47 160.42,126.47 161.17,125.71 161.17,106.67 161.4,106.45 162.18,106.45 162.44,106.71 162.44,130.77 160.8,132.41 160.8,144.86 161.32,145.38 161.32,149.21 159.7,150.83 159.7,157.22 160.69,158.21 160.69,162.68 159.15,164.22 159.15,173.17 157.04,175.28 157.04,177.68 K13.6
D10701: length 210.6
  TOP w0.231: SITE2.70 220.32,216.03 v1(221.32,215.03)
  L07_SIGNAL w0.17: v1(221.32,215.03) 222.07,214.28 224.53,214.28 224.79,214.54 229.46,214.54 230.34,213.67 234.74,213.67 236.73,211.67 246.56,211.67 250.77,207.46 250.77,198.47 255.45,193.79 255.45,161.79 256.48,160.76 256.48,154.09 254.81,152.42 254.81,144.55 256.15,143.2 256.15,97.44 253.16,94.45 238.73,94.45 233.95,89.66 233.95,58.42 D107.01
D10702: length 210.2
  TOP w0.231: SITE2.65 221.53,214.03 222.53,215.03 v1(222.71,215.03)
  L07_SIGNAL w0.17: D107.02 234.71,62.74 234.71,88.9 239,93.18 253.74,93.18 257.14,96.59 257.14,144.71 258.35,145.92 258.35,160.79 256.65,162.48 256.65,194.42 251.6,199.47 251.6,207.81 246.9,212.51 237.08,212.51 236.6,212.99 235.08,214.5 230.83,214.5 229.52,215.81 223.5,215.81 v1(222.71,215.03)
D10703: length 215.1
  TOP w0.231: v1(219.92,215.03) 219.92,214.83 219.52,214.43 SITE2.66
  L07_SIGNAL w0.17: D107.03 237.53,51.84 235.27,51.84 233.19,53.92 233.19,90.42 238.47,95.71 252.94,95.71 255.14,97.9 255.14,142.76 253.79,144.11 253.79,147.23 252.06,148.96 252.06,153.13 253.35,154.42 253.35,164.03 249.57,167.81 249.57,187.57 243.96,193.18 243.96,203.65 242.94,204.67 241.54,204.67 233.43,212.78 229.94,212.78 229.45,213.27 221.68,213.27 v1(219.92,215.03)
D10705: length 282.8
  TOP w0.231: SITE2.61 219.72,212.43 v1(219.92,212.23)
  L07_SIGNAL w0.17: v1(219.92,212.23) 220.15,212 232.66,212 241.09,203.57 242.49,203.57 243.18,202.88 243.18,192.3 248.7,186.78 248.7,167.15 250.77,165.08 250.77,155.57 249.51,154.31 249.51,152 246.33,148.81 246.33,141.36 241.83,136.86 241.83,117.74 242.62,116.94 244.08,116.94 244.71,117.58 244.71,137.49 248.71,141.5 248.71,143.86 249.25,144.4 251.76,144.4 252.25,143.9 252.25,140.71 254.34,138.62 254.34,98.45 252.67,96.78 238.02,96.78 232.43,91.19 232.43,53.6 234.95,51.07 241.84,51.07 D107.05
D10707: length 282.8
  TOP w0.231: v1(222.71,210.63) 221.71,211.63 SITE2.59
  L07_SIGNAL w0.17: v1(222.71,210.63) 232.53,210.63 237.52,205.64 237.52,202.83 240.52,199.82 240.52,193.23 246.5,187.25 246.5,167.15 247.98,165.68 247.98,155.82 248.74,155.05 248.74,152.63 245.53,149.41 245.53,141.93 240.92,137.32 240.92,117.14 242.15,115.9 244.9,115.9 245.94,116.94 245.94,137.69 249.58,141.33 249.58,141.61 249.86,141.9 251.25,141.9 251.46,141.69 251.46,138.42 252.01,137.88 252.01,132.8 253.13,131.68 253.13,99.11 251.98,97.96 237.67,97.96 231.66,91.95 231.66,53.29 234.64,50.31 246.16,50.31 D107.07
D10709: length 282.8
  TOP w0.231: SITE2.58 220.72,211.23 v1(221.32,210.63)
  L07_SIGNAL w0.17: v1(221.32,210.63) 222.11,209.83 224.2,209.83 225.67,208.36 232.96,208.36 236.33,204.99 236.33,202.07 239.09,199.31 239.09,192.75 245.6,186.24 245.6,158.75 246.91,157.44 246.91,155.4 244.56,153.05 244.56,142.08 239.97,137.49 239.97,115.46 241.11,114.32 245.95,114.32 246.91,115.27 246.91,136.64 247.76,137.49 249.92,137.49 250.91,136.51 250.91,132.56 252.26,131.21 252.26,100.29 250.91,98.95 237.14,98.95 230.9,92.71 230.9,52.97 234.32,49.55 250.48,49.55 D107.09
D10711: length 218.8
  TOP w0.231: v1(222.71,209.03) 221.71,210.03 SITE2.55
  L07_SIGNAL w0.17: D107.11 254.8,48.79 234.01,48.79 230.14,52.66 230.14,93.47 232.43,95.77 232.43,118.95 235.65,122.17 235.65,134.34 243.29,141.98 243.29,153.37 241.88,154.79 241.88,165.02 244.65,167.79 244.65,185.1 236.74,193.01 236.74,199.05 235.09,200.69 235.09,204.41 231.99,207.52 225.15,207.52 223.64,209.03 v1(222.71,209.03)
D10713: length 226.1
  TOP w0.231: SITE2.54 220.72,209.63 v1(221.32,209.03)
  L07_SIGNAL w0.17: v1(221.32,209.03) 222.09,208.25 222.88,208.25 226.2,204.93 231.43,204.93 231.73,205.23 233.09,205.23 234.33,204 234.33,200.07 235.85,198.54 235.85,192.49 243.16,185.18 243.16,171.13 240.38,168.34 240.38,164.25 234.27,158.14 234.27,153.27 229.82,148.82 229.82,136.36 231.74,134.43 231.74,127.9 232.67,126.98 232.67,123.61 231.37,122.31 231.37,96.23 229.38,94.23 229.38,50.7 232.05,48.03 259.12,48.03 D107.13
D10715: length 282.8
  TOP w0.231: SITE2.67 215.92,214.83 v1(215.72,214.63)
  L03_SIGNAL w0.145: v1(215.72,214.63) 217.41,214.63 218.55,213.48 218.55,198.5 220.57,196.49 220.57,192.36 226.62,186.31 234.21,186.31 237.42,183.09 239.32,183.09 240.24,182.18 240.24,180.7 UNK2K13.3
  L07_SIGNAL w0.17: D107.15 263.43,47.27 231.73,47.27 228.62,50.38 228.62,65.72 219.55,74.79 219.55,111.24 220.26,111.95 221.31,111.95 221.78,111.47 221.78,96.11 222.67,95.22 224.98,95.22 225.88,96.13 225.88,116.84 230.01,120.96 230.01,122.17 231.81,123.97 231.81,126.62 230.88,127.54 230.88,134.08 228.96,136 228.96,149.18 233.4,153.63 233.4,161.93 237.38,165.91 237.38,169.96 240.2,172.79 240.2,177.64 UNK2K13.3
D10801: length 282.8
  TOP w0.231: SITE2.56 215.92,210.43 v1(215.72,210.23)
  L07_SIGNAL w0.17: D108.01 234.36,37.69 231.92,37.69 231.24,37.01 231.24,29.36 232.01,28.59 257.5,28.59 257.85,28.23 257.85,26.36 257.32,25.83 212.43,25.83 210.33,27.93 210.33,125.66 219.95,135.28 219.95,143.31 218.44,144.82 218.44,175.84 215.32,178.96 215.32,185.67 215.67,186.02 215.67,189.79 215.67,189.79 215.67,199.3 216.44,200.07 216.44,209.5 v1(215.72,210.23)
D10802: length 282.8
  TOP w0.231: SITE2.60 215.92,212.03 v1(215.72,211.83)
  L07_SIGNAL w0.17: D108.02 236.57,40.56 230.95,40.56 230.25,39.86 230.25,27.42 229.73,26.9 223.44,26.9 222.35,28 222.35,49.22 221.93,49.63 218.98,49.63 218.55,49.19 218.55,27.56 217.89,26.9 212.89,26.9 211.09,28.69 211.09,122.15 214.26,125.31 220.17,125.31 221.31,126.45 221.31,143.15 219.14,145.31 219.14,176.13 216.02,179.25 216.02,185.38 216.36,185.73 216.36,198.73 217.07,199.44 217.07,210.48 v1(215.72,211.83)
D10803: length 282.8
  TOP w0.231: v1(215.72,207.03) 215.92,207.23 SITE2.48
  L07_SIGNAL w0.17: v1(215.72,207.03) 215.66,206.97 215.66,200.75 214.29,199.38 214.29,187.84 213.95,187.5 213.95,178.84 216,176.79 216,145.66 218.76,142.9 218.76,135.46 209.57,126.27 209.57,27.03 211.54,25.05 257.99,25.05 258.9,25.96 258.9,29 258.35,29.54 232.74,29.54 232.46,29.82 232.46,33.65 232.99,34.17 240.18,34.17 D108.03
D10804: length 282.8
  TOP w0.231: SITE2.57 219.72,210.83 v1(219.92,210.63)
  L07_SIGNAL w0.17: v1(219.92,210.63) 217.7,208.41 217.7,198.95 217.06,198.31 217.06,185.44 216.72,185.1 216.72,179.53 220.6,175.65 220.6,145.61 222.57,143.64 222.57,125.95 220.9,124.28 218.46,124.28 211.85,117.67 211.85,29.47 213.11,28.22 216.95,28.22 217.54,28.8 217.54,49.84 218.07,50.36 222.55,50.36 223.09,49.82 223.09,29.5 224.38,28.22 228.35,28.22 228.92,28.79 228.92,41.14 229.69,41.91 240.3,41.91 D108.04
D10805: length 282.8
  TOP w0.231: v1(215.72,208.63) 215.92,208.83 SITE2.52
  L07_SIGNAL w0.17: D108.05 243.09,32 237.51,32 236.98,31.47 236.98,30.7 237.32,30.37 258.88,30.37 259.91,29.33 259.91,25.03 259.17,24.29 211.23,24.29 208.81,26.71 208.81,130.89 217.44,139.52 217.44,141.97 215.08,144.33 215.08,176.72 213.25,178.55 213.25,187.79 213.59,188.13 213.59,201.24 214.99,202.63 214.99,207.9 v1(215.72,208.63)
D10806: length 282.8
  TOP w0.231: SITE2.53 219.72,209.23 v1(219.92,209.03)
  L07_SIGNAL w0.17: v1(219.92,209.03) 218.49,207.6 218.49,197.33 219.81,196.01 219.81,187.73 218.31,186.23 218.31,179.87 223.31,174.88 223.31,135.89 223.93,135.27 223.93,132.33 223.74,132.14 223.74,124.84 212.84,113.94 212.84,30.04 213.63,29.26 216.1,29.26 216.58,29.74 216.58,50.21 217.44,51.08 223.32,51.08 223.92,50.48 223.92,30.14 224.79,29.26 227.19,29.26 227.72,29.78 227.72,41.41 229,42.69 244.6,42.69 D108.06
D10807: length 255.8
  TOP w0.231: v1(213.12,205.23) 213.32,205.03 SITE2.40
  L07_SIGNAL w0.17: v1(213.12,205.23) 213.12,202.29 212.62,201.78 212.62,196.6 212.88,196.33 212.88,188.42 212.54,188.08 212.54,145.87 213.28,145.13 213.28,137.11 208.04,131.88 208.04,26.4 210.91,23.53 260.04,23.53 260.78,24.26 260.78,30.83 257.28,34.33 252.96,34.33 D108.07
D10808: length 208
  TOP w0.231: SITE2.49 219.72,207.63 v1(219.92,207.43)
  L07_SIGNAL w0.17: D108.08 248.91,43.46 229.76,43.46 224.81,48.41 224.81,61.19 214.02,71.98 214.02,113.77 224.51,124.26 224.51,127.11 225.09,127.7 225.09,130.91 224.81,131.19 224.81,135.39 224.02,136.19 224.02,175.17 219.02,180.17 219.02,185.94 220.52,187.43 220.52,196.23 219.15,197.6 219.15,206.65 v1(219.92,207.43)
D10809: length 262.1
  L07_SIGNAL w0.17: v1(213.48,213.47) 212.49,212.47 212.49,204.43 210.86,202.81 210.86,145.36 212.13,144.09 212.13,137.11 207.28,132.27 207.28,26.08 210.6,22.77 261.34,22.77 261.97,23.4 261.97,31.16 257.57,35.56 D108.09
D10810: length 210.2
  TOP w0.231: v1(219.92,205.83) 219.72,206.03 SITE2.45
  L07_SIGNAL w0.17: D108.10 253.23,44.22 230.47,44.22 225.57,49.12 225.57,61.77 215.14,72.2 215.14,113.83 225.48,124.17 225.48,126.7 226.4,127.62 226.4,131.5 225.57,132.33 225.57,151.38 226.33,152.15 226.33,177.29 222.52,181.1 222.52,185.67 223.28,186.44 223.28,188.72 221.22,190.79 221.22,196.62 219.92,197.92 v1(219.92,205.83)
D10811: length 282.8
  TOP w0.231: v1(212.92,214.63) 213.93,215.63 SITE2.69
  L07_SIGNAL w0.17: v1(212.92,214.63) 211.23,212.94 211.23,204 210.18,202.95 210.18,142.03 206.52,138.36 206.52,25.77 210.28,22.01 269.14,22.01 271.76,24.63 271.76,30.23 270.09,31.9 264.91,31.9 261.89,34.91 D108.11
D10812: length 221.6
  TOP w0.231: v1(221.32,205.83) 220.72,206.43 SITE2.46
  L07_SIGNAL w0.17: v1(221.32,205.83) 221.32,202.45 224.11,199.66 229.19,199.66 231.87,196.97 231.87,179.45 228.51,176.08 228.51,152.67 226.49,150.65 226.49,132.93 227.09,132.33 227.09,127.03 226.3,126.24 226.3,122.38 216.05,112.12 216.05,72.88 226.33,62.6 226.33,49.43 230.78,44.98 257.55,44.98 D108.12
D10813: length 278.8
  L07_SIGNAL w0.17: D108.13 267.8,35.56 272.64,30.72 272.64,24.16 269.7,21.21 209.84,21.21 205.53,25.52 205.53,139.8 208.37,142.64 208.37,202.55 210.65,204.83 210.65,213.84 v1(213.48,216.67)
D10814: length 228.8
  TOP w0.231: v1(222.71,205.83) 221.71,206.83 SITE2.47
  L07_SIGNAL w0.17: v1(222.71,205.83) 222.71,202.29 223.32,201.68 229.44,201.68 233.37,197.75 233.37,177.67 231.64,175.95 231.64,171.04 229.43,168.83 229.43,152.26 227.39,150.22 227.39,135.38 229.13,133.63 229.13,126.34 227.47,124.68 227.47,122.49 217.25,112.27 217.25,73.54 227.09,63.7 227.09,49.75 231.1,45.74 261.87,45.74 D108.14
D10815: length 294
  TOP w0.231: SITE2.148 193.11,217.23 192.79,216.91 189.65,216.91 188.12,215.39 v1(186.4,215.39)
  L07_SIGNAL w0.17: D108.15 273.55,34.06 273.55,23.5 270.48,20.44 209.52,20.44 204.75,25.2 204.75,140.12 207.6,142.96 207.6,186.63 195.07,199.16 195.07,204.3 188.06,211.31 188.06,213.73 v1(186.4,215.39)
D10816: length 282.8
  TOP w0.231: SITE2.68 214.92,215.23 v1(214.32,214.63)
  L03_SIGNAL w0.145: UNK2K13.6 234.99,182.74 227.8,182.74 216.97,193.57 216.97,212.84 216.09,213.73 215.22,213.73 v1(214.32,214.63)
  L07_SIGNAL w0.17: D108.16 266.19,46.5 231.41,46.5 227.85,50.06 227.85,64.62 218.54,73.93 218.54,112.24 219.6,113.3 221.92,113.3 222.72,112.5 222.72,98.3 223.08,97.93 224.59,97.93 225,98.35 225,118.7 228.83,122.53 228.83,124.89 229.95,126 229.95,133.97 228.21,135.71 228.21,149.88 230.25,151.93 230.25,168.49 232.46,170.7 232.46,175.61 236.04,179.19 UNK2K13.6
